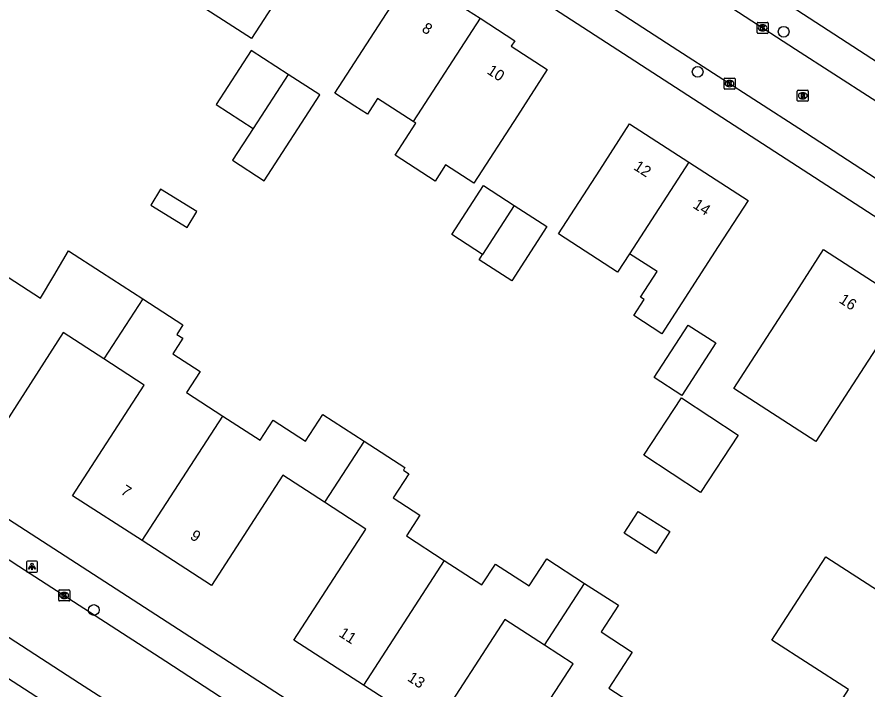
# Model space of a CAD drawing. Extents: x 161141 to 161601, y 381708 to 382245.
# Drawn here: x 161382.4 to 161459.7, y 382024.5 to 382085.7 of the extents above; entities that cross this region are included whole.
import ezdxf

# ---------------------------------------------------------------- set-up
doc = ezdxf.new("R2010")
doc.units = 0
for name, color, linetype in [('IMGEO_Boom', 7, 'Continuous'), ('IMGEO_Kolk', 7, 'Continuous'), ('IMGEO_Lichtpunt', 7, 'Continuous'), ('IMGEO_Pand', 7, 'Continuous'), ('IMGEO_Pand_nummerreeks', 7, 'Continuous'), ('IMGEO_Rijbaan_lokaal_open', 7, 'Continuous'), ('IMGEO_Rioolput', 7, 'Continuous'), ('IMGEO_Voetpad_open', 7, 'Continuous')]:
    doc.layers.add(name, color=color, linetype=linetype)

msp = doc.modelspace()

# ---------------------------------------------------------------- linework, layer by layer
at = {"layer": 'IMGEO_Boom'}
for centre in [(161452.147, 382084.355), (161444.324, 382080.707), (161389.384, 382031.752)]:
    msp.add_circle(centre, 0.489, dxfattribs=at)
at = {"layer": 'IMGEO_Kolk'}
for p, q in [((161449.735, 382084.278), (161449.735, 382085.13)), ((161449.81, 382085.204), (161450.662, 382085.204)), ((161450.223, 382084.984), (161450.248, 382084.984)), ((161450.736, 382085.13), (161450.736, 382084.278)), ((161450.662, 382084.204), (161449.81, 382084.204)), ((161450.246, 382084.424), (161450.221, 382084.424)), ((161446.721, 382079.212), (161446.721, 382080.064)), ((161446.796, 382080.138), (161447.648, 382080.138)), ((161447.209, 382079.918), (161447.234, 382079.918)), ((161447.722, 382080.064), (161447.722, 382079.212)), ((161447.648, 382079.138), (161446.796, 382079.138)), ((161447.232, 382079.358), (161447.207, 382079.358)), ((161386.19, 382032.649), (161386.19, 382033.501)), ((161386.265, 382033.575), (161387.117, 382033.575)), ((161386.678, 382033.355), (161386.703, 382033.355)), ((161387.191, 382033.501), (161387.191, 382032.649)), ((161387.117, 382032.575), (161386.265, 382032.575)), ((161386.701, 382032.795), (161386.676, 382032.795))]:
    msp.add_line(p, q, dxfattribs=at)
for points in [[(161449.735, 382084.278), (161449.735, 382085.13)], [(161449.81, 382085.204), (161450.662, 382085.204)], [(161450.056, 382084.904), (161450.179, 382084.904), (161450.179, 382084.753), (161450.309, 382084.904), (161450.473, 382084.904), (161450.327, 382084.753), (161450.48, 382084.504), (161450.328, 382084.504), (161450.243, 382084.668), (161450.179, 382084.601), (161450.179, 382084.504), (161450.056, 382084.504), (161450.056, 382084.904)], [(161450.736, 382085.13), (161450.736, 382084.278)], [(161450.662, 382084.204), (161449.81, 382084.204)], [(161446.721, 382079.212), (161446.721, 382080.064)], [(161446.796, 382080.138), (161447.648, 382080.138)], [(161447.042, 382079.838), (161447.165, 382079.838), (161447.165, 382079.687), (161447.295, 382079.838), (161447.459, 382079.838), (161447.313, 382079.687), (161447.466, 382079.438), (161447.314, 382079.438), (161447.229, 382079.602), (161447.165, 382079.535), (161447.165, 382079.438), (161447.042, 382079.438), (161447.042, 382079.838)], [(161447.722, 382080.064), (161447.722, 382079.212)], [(161447.648, 382079.138), (161446.796, 382079.138)], [(161386.19, 382032.649), (161386.19, 382033.501)], [(161386.265, 382033.575), (161387.117, 382033.575)], [(161386.511, 382033.275), (161386.634, 382033.275), (161386.634, 382033.124), (161386.764, 382033.275), (161386.928, 382033.275), (161386.782, 382033.124), (161386.935, 382032.875), (161386.783, 382032.875), (161386.698, 382033.039), (161386.634, 382032.972), (161386.634, 382032.875), (161386.511, 382032.875), (161386.511, 382033.275)], [(161387.191, 382033.501), (161387.191, 382032.649)], [(161387.117, 382032.575), (161386.265, 382032.575)]]:
    msp.add_lwpolyline(points, dxfattribs=at)
for centre, start, end in [((161449.812, 382085.128), 91.55205, 178.44795), ((161449.812, 382085.128), 91.55205, 178.44795), ((161450.66, 382085.128), 1.55205, 88.44795), ((161450.66, 382085.128), 1.55205, 88.44795), ((161449.812, 382084.28), 181.55205, 268.44795), ((161449.812, 382084.28), 181.55205, 268.44795), ((161450.66, 382084.28), 271.55205, 358.44795), ((161450.66, 382084.28), 271.55205, 358.44795), ((161446.798, 382080.062), 91.55205, 178.44795), ((161446.798, 382080.062), 91.55205, 178.44795), ((161447.646, 382080.062), 1.55205, 88.44795), ((161447.646, 382080.062), 1.55205, 88.44795), ((161446.798, 382079.214), 181.55205, 268.44795), ((161446.798, 382079.214), 181.55205, 268.44795), ((161447.646, 382079.214), 271.55205, 358.44795), ((161447.646, 382079.214), 271.55205, 358.44795), ((161386.267, 382033.499), 91.55205, 178.44795), ((161386.267, 382033.499), 91.55205, 178.44795), ((161387.115, 382033.499), 1.55205, 88.44795), ((161387.115, 382033.499), 1.55205, 88.44795), ((161386.267, 382032.651), 181.55205, 268.44795), ((161386.267, 382032.651), 181.55205, 268.44795), ((161387.115, 382032.651), 271.55205, 358.44795), ((161387.115, 382032.651), 271.55205, 358.44795)]:
    msp.add_arc(centre, 0.0765, start, end, dxfattribs=at)
for centre, major_axis, ratio, start_param, end_param in [((161450.222, 382084.704), (-0.387, 0.002), 0.722429, 4.712389, 7.853982), ((161450.247, 382084.704), (-0.39, 0.002), 0.717154, 1.570796, 4.712389), ((161447.208, 382079.638), (-0.387, 0.002), 0.722429, 4.712389, 7.853982), ((161447.233, 382079.638), (-0.39, 0.002), 0.717154, 1.570796, 4.712389), ((161386.677, 382033.075), (-0.387, 0.002), 0.722429, 4.712389, 7.853982), ((161386.702, 382033.075), (-0.39, 0.002), 0.717154, 1.570796, 4.712389)]:
    msp.add_ellipse(centre, major_axis=major_axis, ratio=ratio, start_param=start_param, end_param=end_param, dxfattribs=at)
at = {"layer": 'IMGEO_Lichtpunt'}
for p, q in [((161384.164, 382036.198), (161383.356, 382036.198)), ((161384.164, 382036.198), (161383.356, 382036.198)), ((161383.262, 382036.103), (161383.262, 382035.296)), ((161383.262, 382036.103), (161383.262, 382035.296)), ((161384.258, 382035.296), (161384.258, 382036.103)), ((161384.258, 382035.296), (161384.258, 382036.103)), ((161383.356, 382035.202), (161384.164, 382035.202)), ((161383.356, 382035.202), (161384.164, 382035.202))]:
    msp.add_line(p, q, dxfattribs=at)
for points in [[(161383.636, 382035.767), (161383.675, 382035.739), (161383.487, 382035.477), (161383.449, 382035.504), (161383.636, 382035.767)], [(161383.738, 382035.719), (161383.785, 382035.719), (161383.785, 382035.397), (161383.738, 382035.397), (161383.738, 382035.719)], [(161383.848, 382035.739), (161383.886, 382035.766), (161384.073, 382035.504), (161384.034, 382035.476), (161383.848, 382035.739)]]:
    msp.add_lwpolyline(points, dxfattribs=at)
msp.add_circle((161383.761, 382035.901), 0.0994, dxfattribs=at)
for centre, start, end in [((161383.356, 382036.103), 90, 180), ((161383.356, 382036.103), 90, 180), ((161384.164, 382036.103), 0, 90), ((161384.164, 382036.103), 0, 90), ((161383.356, 382035.296), 180, 270), ((161383.356, 382035.296), 180, 270), ((161384.164, 382035.296), 270, 0), ((161384.164, 382035.296), 270, 360)]:
    msp.add_arc(centre, 0.0946, start, end, dxfattribs=at)
at = {"layer": 'IMGEO_Pand'}
for points in [[(161404.008, 382098.017), (161404.764, 382097.529), (161405.713, 382097.732), (161406.876, 382096.98), (161407.084, 382096.013), (161407.959, 382095.447), (161407.856, 382095.287), (161410.219, 382093.759), (161407.505, 382089.561), (161403.739, 382083.736), (161397.438, 382087.809)], [(161418.44, 382076.177), (161415.195, 382078.275), (161414.276, 382076.854), (161413.146, 382077.584), (161411.323, 382078.762), (161415.281, 382084.884), (161417.995, 382089.083), (161421.331, 382086.926), (161421.664, 382087.44), (161424.527, 382085.589)], [(161424.527, 382085.589), (161427.694, 382083.542), (161427.363, 382083.03), (161430.637, 382080.913), (161427.923, 382076.715), (161423.959, 382070.583), (161421.387, 382072.245), (161420.433, 382070.768), (161416.79, 382073.123), (161418.669, 382076.029), (161418.44, 382076.177)], [(161424.527, 382085.589), (161418.44, 382076.177)], [(161407.065, 382080.481), (161403.691, 382082.661), (161400.518, 382077.743), (161403.888, 382075.567)], [(161403.888, 382075.567), (161402.012, 382072.66), (161404.89, 382070.801), (161409.941, 382078.622), (161407.065, 382080.481)], [(161407.065, 382080.481), (161403.888, 382075.567)], [(161438.134, 382064.16), (161437.044, 382062.474), (161431.656, 382065.957), (161435.418, 382071.776), (161438.132, 382075.974), (161443.52, 382072.49)], [(161443.52, 382072.49), (161448.911, 382069.005), (161446.197, 382064.807), (161441.078, 382056.89), (161438.514, 382058.548), (161439.461, 382060.012), (161439.138, 382060.221), (161440.638, 382062.542), (161438.134, 382064.16)], [(161443.52, 382072.49), (161438.134, 382064.16)], [(161424.754, 382064.093), (161421.951, 382065.904), (161424.837, 382070.37), (161427.641, 382068.557)], [(161397.864, 382066.54), (161398.765, 382068.004), (161395.465, 382070.035), (161394.564, 382068.571), (161397.864, 382066.54)], [(161427.641, 382068.557), (161430.604, 382066.641), (161427.412, 382061.705), (161424.449, 382063.621), (161424.754, 382064.093)], [(161427.641, 382068.557), (161424.754, 382064.093)], [(161381.083, 382062.359), (161384.528, 382060.129), (161385.742, 382062.161), (161387.092, 382064.421), (161390.075, 382062.489), (161393.835, 382060.054)], [(161453.071, 382060.334), (161455.786, 382064.533), (161463.24, 382059.714), (161460.525, 382055.515), (161456.345, 382049.049), (161455.075, 382047.085), (161447.621, 382051.906), (161448.89, 382053.869), (161453.071, 382060.334)], [(161393.835, 382060.054), (161390.289, 382054.594)], [(161393.835, 382060.054), (161397.496, 382057.684), (161396.939, 382056.824), (161397.487, 382056.47), (161396.573, 382055.059), (161399.046, 382053.458), (161397.803, 382051.538), (161401.11, 382049.396)], [(161443.461, 382057.675), (161445.976, 382056.048), (161442.884, 382051.265), (161440.368, 382052.892), (161443.461, 382057.675)], [(161390.289, 382054.594), (161386.608, 382056.985), (161380.125, 382046.974), (161373.783, 382051.081)], [(161393.772, 382038.063), (161387.46, 382042.15), (161393.97, 382052.203), (161390.289, 382054.594)], [(161442.858, 382051.048), (161448.016, 382047.664), (161444.589, 382042.441), (161439.431, 382045.825), (161442.858, 382051.048)], [(161393.772, 382038.063), (161401.11, 382049.396)], [(161401.11, 382049.396), (161404.506, 382047.197), (161405.696, 382049.035), (161408.654, 382047.119), (161410.222, 382049.541), (161413.97, 382047.113)], [(161413.97, 382047.113), (161410.358, 382041.557)], [(161413.97, 382047.113), (161417.695, 382044.701), (161417.547, 382044.473), (161418.047, 382044.149), (161416.628, 382041.957), (161419.046, 382040.391), (161417.818, 382038.494), (161421.274, 382036.256)], [(161410.358, 382041.557), (161406.584, 382044.008), (161400.087, 382033.974), (161393.772, 382038.063)], [(161413.923, 382024.909), (161407.591, 382029.009), (161414.13, 382039.106), (161410.358, 382041.557)], [(161440.525, 382036.894), (161437.64, 382038.735), (161438.905, 382040.719), (161441.791, 382038.879), (161440.525, 382036.894)], [(161421.274, 382036.256), (161413.923, 382024.909)], [(161421.274, 382036.256), (161424.699, 382034.038), (161425.925, 382035.931), (161428.991, 382033.945), (161430.587, 382036.409), (161434.04, 382034.173)], [(161460.898, 382022.668), (161459.22, 382020.074), (161456.379, 382021.912), (161458.057, 382024.506), (161451.086, 382029.016), (161453.802, 382033.215), (161455.991, 382036.598), (161466.421, 382029.851)], [(161434.04, 382034.173), (161437.118, 382032.18), (161435.549, 382029.755), (161438.371, 382027.928), (161436.248, 382024.648), (161439.71, 382022.407), (161436.878, 382018.034), (161434.16, 382013.837), (161430.507, 382016.202), (161429.579, 382014.769), (161426.46, 382016.788), (161432.983, 382026.86), (161430.388, 382028.546)], [(161430.388, 382028.546), (161434.04, 382034.173)], [(161430.388, 382028.546), (161426.785, 382030.887), (161420.257, 382020.807), (161413.923, 382024.909)]]:
    msp.add_lwpolyline(points, dxfattribs=at)
at = {"layer": 'IMGEO_Rijbaan_lokaal_open'}
for points in [[(161499.796, 382045.589), (161498.051, 382046.741), (161477.592, 382059.945), (161473.195, 382062.836), (161460.477, 382071.037), (161453.542, 382075.54), (161442.527, 382082.644), (161435.549, 382087.163), (161421.669, 382096.147), (161415.306, 382100.289), (161401.761, 382109.008), (161398.574, 382111.058), (161389.569, 382116.981), (161386.277, 382119.018), (161382.915, 382121.211), (161379.746, 382123.279), (161360.833, 382135.554)], [(161385.362, 382126.757), (161388.136, 382124.895), (161391.361, 382122.845), (161399.992, 382117.288), (161403.197, 382115.21), (161416.21, 382106.739), (161420.597, 382103.968), (161426.931, 382099.82), (161440.905, 382090.804), (161444.055, 382088.754), (161453.24, 382082.778), (161460.192, 382078.284), (161467.324, 382073.702), (161468.287, 382073.003), (161471.488, 382070.983), (161480.028, 382065.466), (161483.251, 382063.426), (161485.554, 382061.86), (161494.669, 382055.998), (161498.469, 382053.534), (161512.078, 382044.654), (161521.765, 382038.348), (161525.596, 382035.854)], [(161311.536, 382081.664), (161356.674, 382052.498), (161362.411, 382048.813), (161375.585, 382040.285), (161382.572, 382035.748), (161395.928, 382027.083), (161402.927, 382022.535), (161416.852, 382013.552), (161420.042, 382011.494), (161421.741, 382010.379), (161425.551, 382007.922), (161458.647, 381986.439), (161460.91, 381984.988)], [(161480.897, 381964.849), (161471.977, 381970.646), (161450.889, 381984.377), (161443.856, 381988.93), (161430.314, 381997.713), (161423.318, 382002.239), (161408.287, 382012.005), (161402.555, 382015.697), (161398.439, 382018.395), (161388.068, 382025.069), (161381.679, 382029.228), (161366.307, 382039.161), (161359.944, 382043.32), (161345.442, 382052.667), (161339.032, 382056.795), (161328.504, 382063.628), (161325.321, 382065.668), (161306.338, 382077.878)]]:
    msp.add_lwpolyline(points, dxfattribs=at)
at = {"layer": 'IMGEO_Rioolput'}
for p, q in [((161453.39, 382078.108), (161453.39, 382078.96)), ((161453.465, 382079.034), (161454.317, 382079.034)), ((161453.878, 382078.814), (161453.903, 382078.814)), ((161454.391, 382078.96), (161454.391, 382078.108)), ((161454.317, 382078.034), (161453.465, 382078.034)), ((161453.901, 382078.254), (161453.876, 382078.254))]:
    msp.add_line(p, q, dxfattribs=at)
for points in [[(161453.39, 382078.108), (161453.39, 382078.96)], [(161453.465, 382079.034), (161454.317, 382079.034)], [(161453.979, 382078.732), (161453.727, 382078.734), (161453.727, 382078.334)], [(161454.391, 382078.96), (161454.391, 382078.108)], [(161454.317, 382078.034), (161453.465, 382078.034)], [(161453.727, 382078.334), (161453.851, 382078.334), (161453.851, 382078.496), (161453.862, 382078.496)], [(161453.905, 382078.653), (161453.851, 382078.653), (161453.851, 382078.572)], [(161453.851, 382078.572), (161453.903, 382078.572)], [(161453.909, 382078.467), (161453.98, 382078.334), (161454.12, 382078.334), (161454.055, 382078.46)]]:
    msp.add_lwpolyline(points, dxfattribs=at)
for centre, radius, start, end in [((161453.467, 382078.958), 0.0765, 91.55205, 178.44795), ((161453.467, 382078.958), 0.0765, 91.55205, 178.44795), ((161453.978, 382078.622), 0.109, 350.36119, 89.41601), ((161454.315, 382078.958), 0.0765, 1.55205, 88.44795), ((161454.315, 382078.958), 0.0765, 1.55205, 88.44795), ((161453.467, 382078.11), 0.0765, 181.55205, 268.44795), ((161453.467, 382078.11), 0.0765, 181.55205, 268.44795), ((161453.861, 382078.443), 0.0533, 26.02933, 88.69889), ((161453.887, 382078.761), 0.19, 274.7715, 282.96867), ((161453.911, 382078.557), 0.0964, 77.00612, 93.18647), ((161453.925, 382078.614), 0.0378, 276.66336, 79.67722), ((161453.976, 382078.622), 0.112, 277.58423, 350.98172), ((161453.96, 382078.407), 0.108, 29.51342, 73.79051), ((161454.315, 382078.11), 0.0765, 271.55205, 358.44795), ((161454.315, 382078.11), 0.0765, 271.55205, 358.44795)]:
    msp.add_arc(centre, radius, start, end, dxfattribs=at)
for centre, major_axis, ratio, start_param, end_param in [((161453.877, 382078.534), (-0.387, 0.002), 0.722429, 4.712389, 7.853982), ((161453.902, 382078.534), (-0.39, 0.002), 0.717154, 1.570796, 4.712389)]:
    msp.add_ellipse(centre, major_axis=major_axis, ratio=ratio, start_param=start_param, end_param=end_param, dxfattribs=at)
at = {"layer": 'IMGEO_Voetpad_open'}
for points in [[(161523.437, 382040.853), (161500, 382056.07), (161450.498, 382088.211), (161408.789, 382114.947), (161389.855, 382127.317), (161365.175, 382143.293), (161365.084, 382143.565)], [(161359.011, 382133.266), (161498.24, 382043.117)], [(161313.623, 382083.997), (161443.483, 382000), (161462.38, 381987.777)], [(161474.804, 381965.241), (161421.048, 382000), (161306.066, 382074.349)]]:
    msp.add_lwpolyline(points, dxfattribs=at)

# ---------------------------------------------------------------- texts
at = {"layer": 'IMGEO_Pand_nummerreeks'}
for s, rotation, p in [('8', 327.12941, (161419.148, 382084.434)), ('10', 327.12941, (161425.081, 382080.597)), ('12', 327.11795, (161438.426, 382071.878)), ('14', 327.11795, (161443.818, 382068.392)), ('16', 327.11739, (161457.115, 382059.768)), ('7', 327.07689, (161391.755, 382042.371)), ('9', 327.07689, (161398.068, 382038.283)), ('11', 327.07451, (161411.606, 382029.412)), ('13', 327.07451, (161417.843, 382025.373))]:
    msp.add_text(s, height=1, rotation=rotation, dxfattribs=at).set_placement(p)

doc.saveas('drawing.dxf')
